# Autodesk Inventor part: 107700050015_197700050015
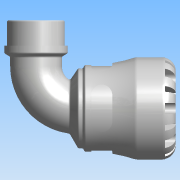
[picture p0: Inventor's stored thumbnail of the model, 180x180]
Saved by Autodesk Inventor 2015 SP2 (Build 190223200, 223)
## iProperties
Created: 2016-12
Part Number: 107700050015_197700050015
Material: PVC-Piping
Description: PLASSON 90° ELBOW WITH MALE INTEGRAL BRASS 50X1.1/2" SERIES 1
Document SubType Name: Modeling
Designer: KIM
Mass: 664.223 g
Surface Area: 733.008 cm^2
Volume: 474.445 cm^3
Density: 1.4 g/cm^3
Appearance: Smooth - White
Author: KIM
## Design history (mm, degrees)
derived "1077.ipt"
feature "Solid1::1077.ipt"
tag "TaggingFeature1"
body "Solid1"
other parameters: "d1" = 33.18, "d3" = 62.5, "d4" = 85, "d8" = 72.25, "d13" = 9, "d14" = 9, "d15" = 0, "d17" = 360 deg, "d19" = 8 deg, "d20" = 1, "d21" = 1, "d22" = 8 deg, "d24" = 0, "d26" = 360 deg, "d33" = 8.5, "d43" = 66.3, "d51" = 0.85, "d54" = 17.5, "d55" = 11, "d57" = 17.64, "d58" = 0, "d74" = 0, "d78" = 79, "d82" = 1, "d115" = 360 deg, "d207" = 90 deg, "d228" = 14.875, "d247" = 1.7, "d248" = 4.74, "d268" = 39.7375, "d269" = 4.74, "d270" = 116, "d276" = 47.803, "d277" = 21, "d278" = 52.5833, "d279" = 73, "d280" = 27.3, "d281" = 7.17045, "d283" = 43.0227, "d286" = 0, "d287" = 0, "d288" = 33.4621, "d290" = 11.63865, "d292" = 30 deg, "d294" = 4.7803, "d296" = 30 deg, "E_" = 85, "l_" = 79, "A_" = 116, "A_1" = 73, "l_2" = 21, "R_" = 47.803, "d9" = 11.25, "d11" = 85, "d12" = 62.5, "d289" = 33.4621
